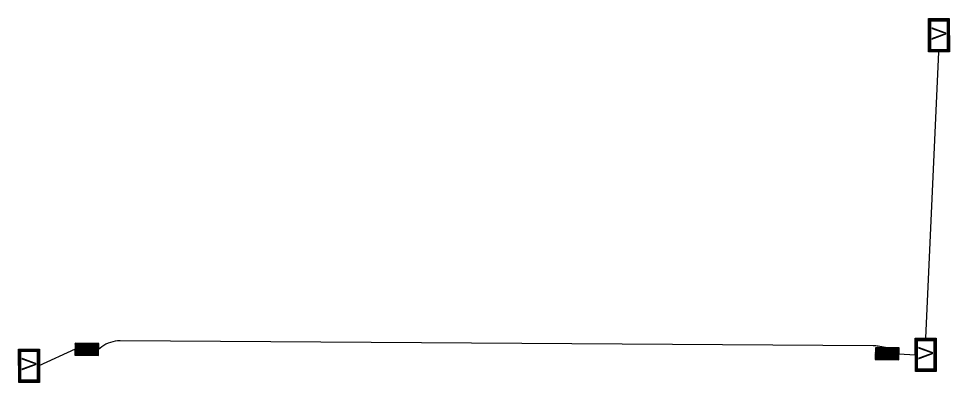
# Model space of a CAD drawing. Extents: x 584850 to 602551, y 145475 to 158627.
# Drawn here: x 585625.9 to 585941, y 157778.9 to 157902.3 of the extents above; entities that cross this region are included whole.
import ezdxf

# ---------------------------------------------------------------- set-up
doc = ezdxf.new("R2010")
doc.units = 0
doc.layers.add('Default', color=7, linetype='Continuous')

msp = doc.modelspace()

# ---------------------------------------------------------------- linework, layer by layer
at = {"layer": 'Default'}
for p, q in [((585933.03, 157793.89), (585937.52, 157890.94)), ((585644.98, 157788.16), (585649.03, 157792.11)), ((585644.99, 157788.5), (585648.69, 157792.12)), ((585644.99, 157788.84), (585648.35, 157792.12)), ((585645, 157789.86), (585647.33, 157792.13)), ((585645, 157789.18), (585648.01, 157792.13)), ((585645, 157789.52), (585647.67, 157792.13)), ((585645.01, 157790.19), (585646.99, 157792.14)), ((585645.01, 157790.53), (585646.65, 157792.14)), ((585645.01, 157790.87), (585646.31, 157792.14)), ((585647.7, 157788.13), (585645.01, 157790.87)), ((585647.36, 157788.13), (585645.01, 157790.53)), ((585645.02, 157791.55), (585645.63, 157792.15)), ((585645.02, 157791.21), (585645.97, 157792.15)), ((585648.38, 157788.12), (585645.02, 157791.55)), ((585648.04, 157788.13), (585645.02, 157791.21)), ((585645.03, 157791.89), (585645.29, 157792.16)), ((585648.72, 157788.12), (585645.03, 157791.89)), ((585649.06, 157788.11), (585645.1, 157792.16)), ((585645.32, 157788.15), (585649.37, 157792.11)), ((585649.4, 157788.11), (585645.44, 157792.15)), ((585645.66, 157788.15), (585649.71, 157792.11)), ((585649.74, 157788.11), (585645.78, 157792.15)), ((585646, 157788.15), (585650.05, 157792.1)), ((585650.08, 157788.1), (585646.12, 157792.15)), ((585646.34, 157788.14), (585650.39, 157792.1)), ((585650.41, 157788.1), (585646.46, 157792.14)), ((585646.68, 157788.14), (585650.72, 157792.1)), ((585650.75, 157788.1), (585646.8, 157792.14)), ((585647.02, 157788.14), (585651.06, 157792.09)), ((585651.09, 157788.09), (585647.14, 157792.14)), ((585647.36, 157788.13), (585651.4, 157792.09)), ((585651.43, 157788.09), (585647.48, 157792.13)), ((585647.7, 157788.13), (585651.74, 157792.09)), ((585651.77, 157788.08), (585647.82, 157792.13)), ((585648.04, 157788.13), (585652.08, 157792.08)), ((585652.11, 157788.08), (585648.16, 157792.12)), ((585648.38, 157788.12), (585652.42, 157792.08)), ((585652.45, 157788.08), (585648.49, 157792.12)), ((585648.72, 157788.12), (585652.76, 157792.07)), ((585652.79, 157788.07), (585648.83, 157792.12)), ((585649.06, 157788.11), (585653.03, 157792)), ((585652.99, 157788.22), (585649.17, 157792.11)), ((585649.4, 157788.11), (585653.02, 157791.66)), ((585652.99, 157788.56), (585649.51, 157792.11)), ((585649.74, 157788.11), (585653.02, 157791.32)), ((585652.99, 157788.9), (585649.85, 157792.11)), ((585650.08, 157788.1), (585653.02, 157790.98)), ((585653, 157789.24), (585650.19, 157792.1)), ((585650.41, 157788.1), (585653.01, 157790.64)), ((585653, 157789.57), (585650.53, 157792.1)), ((585653, 157789.91), (585650.87, 157792.09)), ((585653.01, 157790.25), (585651.21, 157792.09)), ((585653.01, 157790.59), (585651.55, 157792.09)), ((585653.02, 157790.93), (585651.89, 157792.08)), ((585653.02, 157791.27), (585652.23, 157792.08)), ((585653.02, 157791.61), (585652.57, 157792.08)), ((585653.03, 157791.95), (585652.91, 157792.07)), ((585654.1, 157790.91), (585653.01, 157790.07)), ((585915.29, 157791.32), (585660.25, 157792.97)), ((585915.95, 157787.01), (585919.65, 157790.63)), ((585915.95, 157787.35), (585919.31, 157790.63)), ((585915.95, 157786.67), (585919.99, 157790.62)), ((585915.96, 157788.36), (585918.29, 157790.64)), ((585915.96, 157788.02), (585918.63, 157790.64)), ((585915.96, 157787.68), (585918.97, 157790.63)), ((585915.97, 157788.7), (585917.95, 157790.65)), ((585915.97, 157789.04), (585917.61, 157790.65)), ((585915.98, 157790.06), (585916.6, 157790.66)), ((585915.98, 157789.72), (585916.94, 157790.66)), ((585915.98, 157789.38), (585917.27, 157790.65)), ((585915.99, 157790.4), (585916.26, 157790.66)), ((585919.68, 157786.63), (585915.99, 157790.4)), ((585920.02, 157786.62), (585916.06, 157790.67)), ((585916.29, 157786.66), (585920.33, 157790.62)), ((585920.36, 157786.62), (585916.4, 157790.66)), ((585916.63, 157786.66), (585920.67, 157790.62)), ((585920.7, 157786.62), (585916.74, 157790.66)), ((585916.96, 157786.66), (585921.01, 157790.61)), ((585919.99, 157790.62), (585916.98, 157791.16)), ((585921.04, 157786.61), (585917.08, 157790.65)), ((585917.3, 157786.65), (585921.35, 157790.61)), ((585921.38, 157786.61), (585917.42, 157790.65)), ((585917.64, 157786.65), (585921.69, 157790.6)), ((585921.72, 157786.6), (585917.76, 157790.65)), ((585917.98, 157786.64), (585922.03, 157790.6)), ((585922.06, 157786.6), (585918.1, 157790.64)), ((585918.32, 157786.64), (585922.37, 157790.6)), ((585922.4, 157786.6), (585918.44, 157790.64)), ((585918.66, 157786.64), (585922.7, 157790.59)), ((585922.73, 157786.59), (585918.78, 157790.64)), ((585919, 157786.63), (585923.04, 157790.59)), ((585923.07, 157786.59), (585919.12, 157790.63)), ((585919.34, 157786.63), (585923.38, 157790.59)), ((585923.41, 157786.59), (585919.46, 157790.63)), ((585919.68, 157786.63), (585923.72, 157790.58)), ((585923.75, 157786.58), (585919.8, 157790.63)), ((585920.02, 157786.62), (585923.99, 157790.51)), ((585923.95, 157786.73), (585920.14, 157790.62)), ((585923.95, 157787.07), (585920.48, 157790.62)), ((585923.95, 157787.4), (585920.81, 157790.61)), ((585923.96, 157787.74), (585921.15, 157790.61)), ((585923.96, 157788.08), (585921.49, 157790.61)), ((585923.97, 157788.42), (585921.83, 157790.6)), ((585923.97, 157788.76), (585922.17, 157790.6)), ((585923.97, 157789.1), (585922.51, 157790.6)), ((585923.98, 157789.44), (585922.85, 157790.59)), ((585923.98, 157789.78), (585923.19, 157790.59)), ((585923.98, 157790.12), (585923.53, 157790.58)), ((585923.99, 157790.46), (585923.87, 157790.58)), ((585645.01, 157790.16), (585632.79, 157784.48)), ((585645.66, 157788.15), (585644.99, 157788.84)), ((585645.32, 157788.15), (585644.99, 157788.5)), ((585646.68, 157788.14), (585645, 157789.86)), ((585646.34, 157788.14), (585645, 157789.52)), ((585646, 157788.15), (585645, 157789.18)), ((585647.02, 157788.14), (585645.01, 157790.19)), ((585650.75, 157788.1), (585653.01, 157790.3)), ((585651.09, 157788.09), (585653, 157789.96)), ((585651.43, 157788.09), (585653, 157789.62)), ((585651.77, 157788.08), (585653, 157789.28)), ((585652.11, 157788.08), (585652.99, 157788.94)), ((585652.45, 157788.08), (585652.99, 157788.6)), ((585652.79, 157788.07), (585652.99, 157788.26)), ((585916.63, 157786.66), (585915.95, 157787.35)), ((585917.64, 157786.65), (585915.96, 157788.36)), ((585917.3, 157786.65), (585915.96, 157788.02)), ((585916.96, 157786.66), (585915.96, 157787.68)), ((585918.32, 157786.64), (585915.97, 157789.04)), ((585917.98, 157786.64), (585915.97, 157788.7)), ((585919.34, 157786.63), (585915.98, 157790.06)), ((585919, 157786.63), (585915.98, 157789.72)), ((585918.66, 157786.64), (585915.98, 157789.38)), ((585920.36, 157786.62), (585923.98, 157790.17)), ((585920.7, 157786.62), (585923.98, 157789.83)), ((585921.04, 157786.61), (585923.98, 157789.49)), ((585921.38, 157786.61), (585923.97, 157789.15)), ((585921.72, 157786.6), (585923.97, 157788.81)), ((585922.06, 157786.6), (585923.97, 157788.47)), ((585922.4, 157786.6), (585923.96, 157788.13)), ((585922.73, 157786.59), (585923.96, 157787.79)), ((585923.07, 157786.59), (585923.96, 157787.45)), ((585923.97, 157788.58), (585929.51, 157788.23)), ((585916.29, 157786.66), (585915.95, 157787.01)), ((585923.41, 157786.59), (585923.95, 157787.11)), ((585923.75, 157786.58), (585923.95, 157786.77))]:
    msp.add_line(p, q, dxfattribs=at)
for points in [[(585934, 157890.93), (585933.98, 157902.24), (585941.02, 157902.25), (585941.04, 157890.95)], [(585934.25, 157891.18), (585934.23, 157901.99), (585940.77, 157902), (585940.79, 157891.2)], [(585934.5, 157891.43), (585934.48, 157901.74), (585940.52, 157901.75), (585940.54, 157891.45)], [(585934.75, 157891.68), (585934.73, 157901.49), (585940.27, 157901.5), (585940.29, 157891.7)], [(585929.52, 157782.58), (585929.5, 157793.88), (585936.55, 157793.9), (585936.57, 157782.59)], [(585929.77, 157782.83), (585929.75, 157793.64), (585936.3, 157793.65), (585936.32, 157782.84)], [(585653.03, 157792.07), (585645.03, 157792.16), (585644.98, 157788.16), (585652.98, 157788.07)], [(585923.99, 157790.58), (585915.99, 157790.67), (585915.95, 157786.67), (585923.95, 157786.58)], [(585930.02, 157783.08), (585930, 157793.39), (585936.05, 157793.4), (585936.07, 157783.09)], [(585930.27, 157783.33), (585930.25, 157793.14), (585935.8, 157793.15), (585935.82, 157783.34)], [(585625.94, 157778.89), (585625.92, 157790.19), (585632.96, 157790.21), (585632.98, 157778.9)], [(585626.19, 157779.14), (585626.17, 157789.95), (585632.71, 157789.96), (585632.73, 157779.15)], [(585626.44, 157779.39), (585626.42, 157789.7), (585632.46, 157789.71), (585632.48, 157779.4)], [(585626.69, 157779.64), (585626.67, 157789.45), (585632.21, 157789.46), (585632.23, 157779.65)]]:
    msp.add_lwpolyline(points, close=True, dxfattribs=at)
for centre, start, end in [((585660.19, 157782.98), 89.6276, 127.4574), ((585915.22, 157781.32), 79.8561, 89.6276)]:
    msp.add_arc(centre, 10, start, end, dxfattribs=at)

# ---------------------------------------------------------------- texts
for p in [(585939.99, 157894.98), (585935.52, 157786.62), (585631.93, 157782.93)]:
    msp.add_text('V', height=4.96, rotation=90.1102, dxfattribs=at).set_placement(p)

doc.saveas('drawing.dxf')
